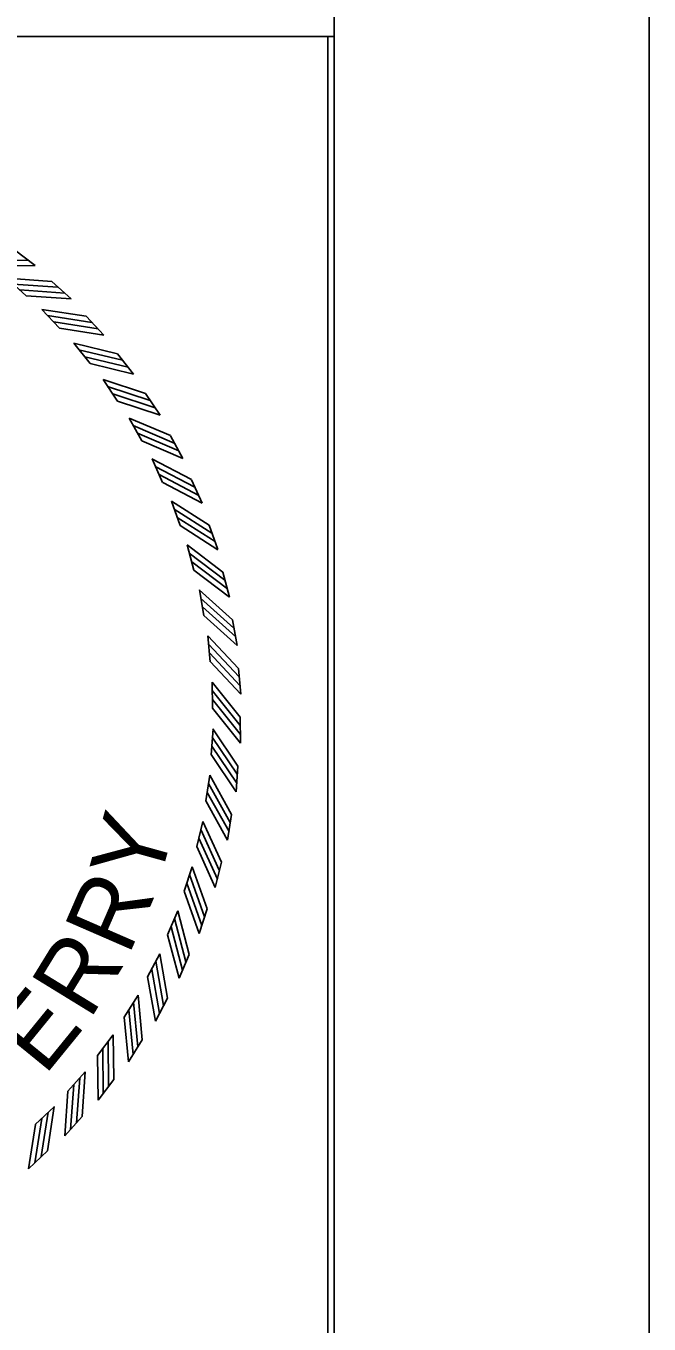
# Model space of a CAD drawing. Extents: x 0 to 1228740, y 0 to 152440.
# Drawn here: x 32.858 to 34, y 17.785 to 20.163 of the extents above; entities that cross this region are included whole.
import ezdxf

# ---------------------------------------------------------------- set-up
doc = ezdxf.new("R2010")
doc.units = 0
for name, color, linetype in [('R_Border', 7, 'Continuous'), ('R_No Plot', 7, 'Continuous'), ('STAMP', 7, 'Continuous'), ('STAMP_KLL', 7, 'Continuous')]:
    doc.layers.add(name, color=color, linetype=linetype)

# ---------------------------------------------------------------- blocks, each defined once
blk = doc.blocks.new('AR_SPT')
at = {"layer": 'R_No Plot'}
blk.add_lwpolyline([(-0.10028, 0.09468), (0.09697, 0.09468), (0.09697, -0.10257), (-0.10028, -0.10257)], close=True, dxfattribs=at)
at = {"layer": 'STAMP'}
for p, q in [((0.05144, 0.06366), (0.05443, 0.06137)), ((0.05033, 0.05951), (0.05313, 0.05698)), ((0.05683, 0.05904), (0.05963, 0.05652)), ((0.05539, 0.05501), (0.05797, 0.05225)), ((0.06183, 0.054), (0.0644, 0.05125)), ((0.06005, 0.05009), (0.0624, 0.04714)), ((0.06639, 0.04856), (0.06873, 0.04561)), ((0.0643, 0.04481), (0.06639, 0.04167)), ((0.07048, 0.04276), (0.07257, 0.03963)), ((0.06809, 0.0392), (0.06992, 0.0359)), ((0.07408, 0.03664), (0.07591, 0.03335)), ((0.07141, 0.0333), (0.07295, 0.02985)), ((0.07717, 0.03025), (0.07871, 0.02682)), ((0.07422, 0.02713), (0.07548, 0.02358)), ((0.07971, 0.02363), (0.08097, 0.02008)), ((0.07652, 0.02076), (0.07748, 0.01711)), ((0.08171, 0.01681), (0.08266, 0.01317)), ((0.07829, 0.01422), (0.07894, 0.01051)), ((0.08313, 0.00986), (0.08378, 0.00615)), ((0.07951, 0.00756), (0.07985, 0.0038)), ((0.08397, 0.00281), (0.08431, -0.00094)), ((0.08017, 0.00082), (0.08021, -0.00295)), ((0.08423, -0.00428), (0.08426, -0.00805)), ((0.08028, -0.00595), (0.08, -0.00972)), ((0.07982, -0.01271), (0.07924, -0.01644)), ((0.0839, -0.01137), (0.08362, -0.01513)), ((0.08298, -0.01841), (0.0824, -0.02213)), ((0.07881, -0.01941), (0.07792, -0.02308)), ((0.07725, -0.026), (0.07606, -0.02958)), ((0.08149, -0.02535), (0.0806, -0.02901)), ((0.07515, -0.03244), (0.07367, -0.03591)), ((0.07943, -0.03214), (0.07824, -0.03572)), ((0.07253, -0.03869), (0.07076, -0.04202)), ((0.07682, -0.03874), (0.07534, -0.0422)), ((0.0694, -0.04469), (0.06736, -0.04787)), ((0.07367, -0.0451), (0.0719, -0.04843)), ((0.06578, -0.05042), (0.06349, -0.05342)), ((0.07, -0.05118), (0.06797, -0.05435)), ((0.06171, -0.05583), (0.05917, -0.05863)), ((0.06585, -0.05694), (0.06356, -0.05993)), ((0.0572, -0.06089), (0.05444, -0.06347)), ((0.06123, -0.06233), (0.05871, -0.06512)), ((0.05619, -0.06732), (0.05344, -0.0699))]:
    blk.add_line(p, q, dxfattribs=at)
for points in [[(0.04693, 0.06208), (0.05345, 0.06214)], [(0.04792, 0.06131), (0.05444, 0.06137)], [(0.05033, 0.05952), (0.05683, 0.05904)], [(0.05122, 0.05869), (0.05772, 0.05822)], [(0.05221, 0.05784), (0.05871, 0.05737)], [(0.05313, 0.05699), (0.05963, 0.05652)], [(0.05538, 0.05501), (0.06182, 0.054)], [(0.0562, 0.05411), (0.06264, 0.05311)], [(0.05712, 0.05318), (0.06356, 0.05217)], [(0.05797, 0.05226), (0.06441, 0.05125)], [(0.06005, 0.0501), (0.06638, 0.04856)], [(0.06079, 0.04914), (0.06712, 0.0476)], [(0.06163, 0.04813), (0.06796, 0.0466)], [(0.0624, 0.04714), (0.06873, 0.04561)], [(0.06429, 0.04482), (0.07048, 0.04276)], [(0.06495, 0.0438), (0.07114, 0.04175)], [(0.0657, 0.04273), (0.07189, 0.04068)], [(0.06639, 0.04168), (0.07257, 0.03963)], [(0.06808, 0.0392), (0.07408, 0.03665)], [(0.06866, 0.03814), (0.07465, 0.03558)], [(0.06932, 0.03701), (0.07531, 0.03445)], [(0.06992, 0.0359), (0.07591, 0.03335)], [(0.0714, 0.0333), (0.07716, 0.03026)], [(0.07189, 0.03219), (0.07765, 0.02915)], [(0.07245, 0.03101), (0.07821, 0.02796)], [(0.07296, 0.02986), (0.07872, 0.02682)], [(0.07422, 0.02714), (0.07971, 0.02363)], [(0.07461, 0.02599), (0.0801, 0.02248)], [(0.07508, 0.02477), (0.08057, 0.02126)], [(0.07548, 0.02358), (0.08097, 0.02007)], [(0.07652, 0.02077), (0.0817, 0.01682)], [(0.07682, 0.01959), (0.082, 0.01564)], [(0.07718, 0.01833), (0.08236, 0.01438)], [(0.07748, 0.01712), (0.08267, 0.01317)], [(0.07828, 0.01423), (0.08312, 0.00986)], [(0.07848, 0.01303), (0.08332, 0.00867)], [(0.07874, 0.01175), (0.08358, 0.00739)], [(0.07895, 0.01051), (0.08378, 0.00615)], [(0.0795, 0.00756), (0.08396, 0.00282)], [(0.0796, 0.00636), (0.08406, 0.00161)], [(0.07975, 0.00506), (0.08421, 0.00031)], [(0.07986, 0.00381), (0.08432, -0.00094)], [(0.08017, 0.00082), (0.08422, -0.00428)], [(0.08017, -0.00039), (0.08422, -0.00549)], [(0.08021, -0.0017), (0.08426, -0.0068)], [(0.08021, -0.00295), (0.08426, -0.00805)], [(0.08017, -0.00716), (0.08379, -0.01257)], [(0.08027, -0.00595), (0.08389, -0.01137)], [(0.08011, -0.00846), (0.08373, -0.01388)], [(0.08, -0.00971), (0.08362, -0.01513)], [(0.07982, -0.01271), (0.08298, -0.01841)], [(0.07962, -0.0139), (0.08278, -0.0196)], [(0.07924, -0.01644), (0.0824, -0.02214)], [(0.07945, -0.0152), (0.08261, -0.0209)], [(0.07851, -0.02058), (0.08119, -0.02652)], [(0.07881, -0.01941), (0.08149, -0.02534)], [(0.07823, -0.02186), (0.08091, -0.0278)], [(0.07792, -0.02307), (0.0806, -0.02901)], [(0.07725, -0.026), (0.07943, -0.03214)], [(0.07686, -0.02714), (0.07903, -0.03328)], [(0.07606, -0.02958), (0.07824, -0.03572)], [(0.07647, -0.02839), (0.07865, -0.03453)], [(0.07466, -0.03355), (0.07633, -0.03985)], [(0.07515, -0.03244), (0.07682, -0.03874)], [(0.07418, -0.03476), (0.07584, -0.04106)], [(0.07367, -0.03591), (0.07534, -0.04221)], [(0.07253, -0.03868), (0.07367, -0.0451)], [(0.07136, -0.04092), (0.0725, -0.04733)], [(0.07195, -0.03975), (0.07309, -0.04616)], [(0.07077, -0.04202), (0.07191, -0.04844)], [(0.0694, -0.04469), (0.07, -0.05118)], [(0.06805, -0.04682), (0.06866, -0.05331)], [(0.06873, -0.0457), (0.06934, -0.05219)], [(0.06737, -0.04787), (0.06797, -0.05436)], [(0.06578, -0.05042), (0.06585, -0.05693)], [(0.06427, -0.05243), (0.06433, -0.05894)], [(0.06504, -0.05137), (0.0651, -0.05789)], [(0.0635, -0.05342), (0.06356, -0.05993)], [(0.06171, -0.05583), (0.06123, -0.06232)], [(0.06003, -0.05771), (0.05956, -0.06421)], [(0.06089, -0.05672), (0.06041, -0.06322)], [(0.05918, -0.05863), (0.05871, -0.06513)], [(0.05631, -0.0617), (0.0553, -0.06814)], [(0.0572, -0.06088), (0.05619, -0.06732)], [(0.05445, -0.06347), (0.05344, -0.0699)], [(0.05537, -0.06262), (0.05436, -0.06905)]]:
    blk.add_lwpolyline(points, dxfattribs=at)
for s, rotation, p in [('Y', 74.5264, (0.07226, -0.02906)), ('R', 66.5008, (0.06798, -0.0391)), ('R', 58.4752, (0.06233, -0.04844)), ('E', 50.8144, (0.05577, -0.05653))]:
    blk.add_text(s, height=0.0104, rotation=rotation, dxfattribs=at).set_placement(p)

msp = doc.modelspace()

# ---------------------------------------------------------------- linework, layer by layer
at = {"layer": 'R_Border'}
for p, q in [((33.4231, 0.5768), (33.4231, 21.4232)), ((29.1131, 20.1432), (33.4231, 20.1432))]:
    msp.add_line(p, q, dxfattribs=at)
msp.add_lwpolyline([(34, 22), (0, 22), (0, 0), (34, 0)], close=True, dxfattribs=at)

# ---------------------------------------------------------------- block references
at = {"layer": 'STAMP_KLL', "xscale": 12.6035, "yscale": 12.6035}
msp.add_blockref('AR_SPT', (32.1893, 18.9501), dxfattribs=at)

doc.saveas('drawing.dxf')
